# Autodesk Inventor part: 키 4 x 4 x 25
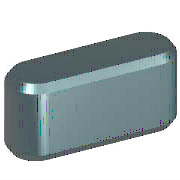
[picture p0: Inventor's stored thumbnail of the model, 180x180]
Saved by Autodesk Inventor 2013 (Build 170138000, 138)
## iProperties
IsCustomPart: 1
Created: 2012-02
Part Number: 키 4 x 4 x 25
Material: 강철, 연강
Description: 키 및 해당 키홈
Document SubType Name: Modeling
Standard: KS B 1311
Designer: mduedu
Standards Organization: KS
Language: ko-KR
Size Designation: 4 x 4 x 25
Categories: <MemberInstance><Categories><Category DisplayName="샤프트 부품" InternalName="7f7aeb1f-a693-4053-b835-cee3144e0d98" Mnemonic="SHFT"><Category DisplayName="키" Interna
Density: 1 g/cm^3
Author: mduedu
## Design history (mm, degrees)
workplane "Work Plane1"
workplane "Work Plane2"
sketch "스케치1"
  geometry: L1 (2, 2)-(23, 2); L2 (23, -2)-(2, -2); L3 (0, 9.4)-(0, -7.4) reference; L4 (-5, 0)-(30, 0) reference; L5 (25, 0)-(25, 7); A1 r 2 centre (2, 0) between (2, 2) and (2, -2); A2 r 2 centre (23, 0) between (23, -2) and (23, 2)
  constraints: 6 end point, 5 point on circle, 4 tangent, 3 point on line, 2 centre point, 1 horizontal, 1 parallel, 1 perpendicular
  dimensions: "d0" = 2 radius of A1 (= 0.5 x PB); "d13" = 2 radius of A2 (= 0.5 x PB); "d14" = 25 distance between parallel lines of L5 L3 (= NLG)
extrude "본체1" new body sketch "스케치1" taper "d3" = 0 deg; stored distance "d4" = 10
workplane "Work Plane3"
body "Solid1"
chamfer "모따기1" distance "d8" = 0.25 (= PHH); stored, may be unused: second distance "d9" = 0.25 (= PHH), angle "d15" = 45 deg
other parameters: "d1" = -2.5 (= -PNT), "d2" = 1.5 (= PH - PNT), "NLG" = 25 [user parameter; used in 3 equation terms], "PB" = 4 [user parameter; used in 2 equation terms], "PNT" = 2.5 [user parameter; used in 2 equation terms], "PH" = 4 [user parameter; used in 1 equation term], "PHH" = 0.25 [user parameter; used in 2 equation terms], "d10" = 0, "d16" = 0, "d17" = 0, "d18" = 0, "PLB2" = 25 (= NLG) [user parameter], "WDMAX" = 12 [user parameter], "PLB1" = 25 (= NLG) [user parameter], "RR" = 0.08 [user parameter], "PUEB" = 1.8 [user parameter]
